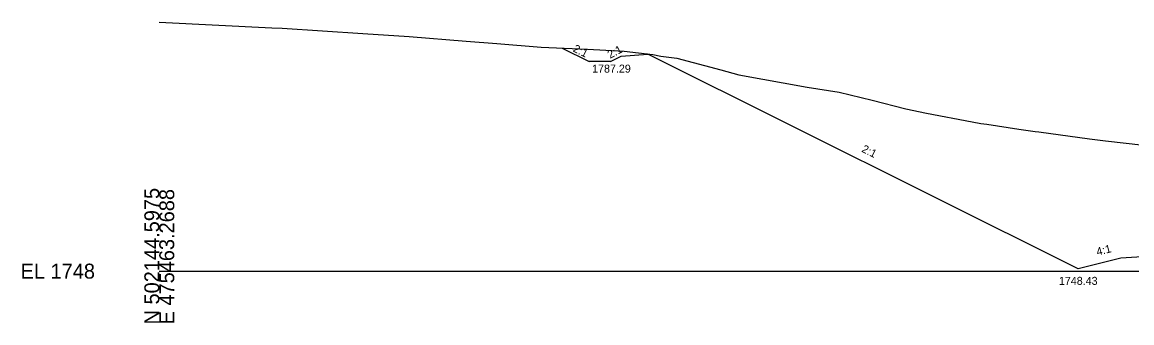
# Model space of a CAD drawing. Extents: x -26 to 1803, y -10 to 9558.
# Drawn here: x -25.7 to 182.2, y 7990.3 to 8046.7 of the extents above; entities that cross this region are included whole.
import ezdxf

# ---------------------------------------------------------------- set-up
doc = ezdxf.new("R2010")
doc.units = 0
for name, color, linetype in [('Exist Cross Section Cell', 7, 'Continuous'), ('Exist XS Ground Line', 7, 'Continuous'), ('Prop XS DDE', 7, 'Continuous'), ('Prop XS Ditch Slope Text', 7, 'Continuous'), ('Prop XS Ditch Standard Text', 7, 'Continuous'), ('Prop XS Dump Level', 7, 'Continuous'), ('Prop XS Earthwork Shape', 7, 'Continuous'), ('Prop XS Finish Grade Earthwork', 7, 'Continuous'), ('Prop XS Hydro Typical Ditch Data', 7, 'Continuous'), ('Prop XS Side Slope Text', 7, 'Continuous')]:
    doc.layers.add(name, color=color, linetype=linetype)

msp = doc.modelspace()

# ---------------------------------------------------------------- linework, layer by layer
at = {"layer": 'Exist Cross Section Cell'}
msp.add_line((0, 8000), (200, 8000), dxfattribs=at)
at = {"layer": 'Exist XS Ground Line'}
msp.add_lwpolyline([(0, 8046.69), (21.1, 8045.64), (23.01, 8045.57), (38.17, 8044.56), (46.83, 8043.98), (57.49, 8043.14), (63.26, 8042.71), (71.57, 8042.01), (80.24, 8041.63), (87.09, 8041.24), (92.47, 8040.6), (93.99, 8040.3), (96.97, 8039.92), (105.2, 8037.73), (108.6, 8036.79), (121.37, 8034.53), (127.4, 8033.54), (133.61, 8032.04), (139.87, 8030.44), (143.79, 8029.6), (152.34, 8027.97), (153.96, 8027.71), (155.07, 8027.56), (161.09, 8026.64), (164.13, 8026.2), (164.81, 8026.1), (174.3, 8024.78), (177.28, 8024.46), (184.47, 8023.62)], dxfattribs=at)
at = {"layer": 'Prop XS DDE'}
for p, q in [((75.48, 8041.84), (80.57, 8039.29)), ((86.57, 8040.29), (91.57, 8040.71)), ((84.57, 8039.29), (80.57, 8039.29)), ((84.57, 8039.29), (86.57, 8040.29))]:
    msp.add_line(p, q, dxfattribs=at)
at = {"layer": 'Prop XS Earthwork Shape'}
msp.add_lwpolyline([(184.15, 8002.68), (180.17, 8002.43), (172.17, 8000.43), (91.57, 8040.71), (92.47, 8040.6), (93.99, 8040.3), (96.97, 8039.92), (105.2, 8037.73), (108.6, 8036.79), (121.37, 8034.53), (127.4, 8033.54), (133.61, 8032.04), (139.87, 8030.44), (143.79, 8029.6), (152.34, 8027.97), (153.96, 8027.71), (155.07, 8027.56), (161.09, 8026.64), (164.13, 8026.2), (164.81, 8026.1), (174.3, 8024.78), (177.28, 8024.46), (184.47, 8023.62)], dxfattribs=at)
at = {"layer": 'Prop XS Finish Grade Earthwork'}
for p, q in [((172.17, 8000.43), (91.57, 8040.71)), ((180.17, 8002.43), (172.17, 8000.43)), ((184.15, 8002.68), (180.17, 8002.43))]:
    msp.add_line(p, q, dxfattribs=at)
at = {"layer": 'Prop XS Hydro Typical Ditch Data'}
for p, q in [((172.17, 8000.43), (91.57, 8040.71)), ((180.17, 8002.43), (172.17, 8000.43))]:
    msp.add_line(p, q, dxfattribs=at)

# ---------------------------------------------------------------- texts
at = {"layer": 'Exist Cross Section Cell'}
for s, p in [('N 502144.5975', (0, 7990)), ('E 475463.2688', (2.8, 7990))]:
    msp.add_text(s, height=2.8, rotation=90, dxfattribs=at).set_placement(p)
msp.add_text('EL 1748', height=2.8, dxfattribs=at).set_placement((-26, 7998.6))
at = {"layer": 'Prop XS Ditch Slope Text'}
msp.add_text('4:1', height=1.5, rotation=14.0308, dxfattribs=at).set_placement((175.8, 8002.89))
at = {"layer": 'Prop XS Ditch Standard Text'}
for s, p in [('1787.29', (81.1, 8037.23)), ('1748.43', (168.57, 7997.43))]:
    msp.add_text(s, height=1.5, dxfattribs=at).set_placement(p)
at = {"layer": 'Prop XS Dump Level'}
msp.add_text('Case1', height=0.04, dxfattribs=at).set_placement((180.17, 8002.39))
at = {"layer": 'Prop XS Side Slope Text'}
for rotation, p in [(333.4349, (77.38, 8041.25)), (28.5444, (84.47, 8039.8)), (28.5444, (84.47, 8039.8)), (333.4443, (131.48, 8022.44))]:
    msp.add_text('2:1', height=1.5, rotation=rotation, dxfattribs=at).set_placement(p)

doc.saveas('drawing.dxf')
